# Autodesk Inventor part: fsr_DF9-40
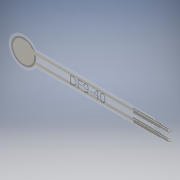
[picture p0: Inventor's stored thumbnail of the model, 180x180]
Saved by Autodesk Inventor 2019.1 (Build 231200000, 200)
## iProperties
Created: 2018-09
Part Number: fsr_DF9-40
Material: Polycarbonate, Clear
Document SubType Name: Modeling
Designer: Ev
Density: 1.2 g/cm^3
Appearance: Polycarbonate - Clear
Author: Ev
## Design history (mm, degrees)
sketch "Sketch1"
  geometry: L1 (-14.266, 18.616)-(39.487, 18.616); L2 (39.487, 18.616)-(39.487, -35.137); L3 (39.487, -35.137)-(-14.266, -35.137); L4 (-14.266, -35.137)-(-14.266, 18.616); L5 (40.115, 2.406)-(3.888, 2.393); L6 (3.922, -2.407)-(40.115, -2.394); L7 (40.115, -2.394)-(40.115, 2.406); L8 (0.115, -0.042)-(46.724, -0.042); L9 (3.503, 1.565)-(40.115, 1.565); L10 (40.115, 1.565)-(40.115, 0.865); L11 (40.115, 0.865)-(3.753, 0.865); L12 (3.503, -1.65)-(40.115, -1.65); L13 (40.115, -0.95)-(3.753, -0.95); L14 (33.615, 1.915)-(39.615, 1.915); L15 (39.615, 1.915)-(39.615, 0.515); L16 (39.615, 0.515)-(33.615, 0.515); L17 (33.615, 0.515)-(33.615, 1.915); L18 (33.615, -2)-(39.615, -2); L19 (33.615, -0.6)-(33.615, -2); L20 (39.615, -0.6)-(33.615, -0.6); L21 (39.615, -2)-(39.615, -0.6); L22 (33.949, 1.71)-(41.92, 1.71); L23 (42.115, 0.865)-(42.115, 0.88); L24 (41.872, 0.71)-(33.949, 0.71); L25 (33.949, 0.71)-(33.949, 1.71); L26 (42.115, 1.574)-(44.387, 1.574); L27 (44.387, 0.88)-(42.115, 0.88); L28 (42.115, 0.88)-(42.115, 0.865); L29 (42.115, 1.574)-(41.92, 1.71); L30 (42.115, 1.574)-(42.352, 1.574); L31 (42.115, 0.88)-(41.872, 0.71); L32 (42.115, 0.88)-(42.411, 0.88); L33 (45.146, 1.322)-(44.387, 1.574); L34 (45.146, 1.133)-(44.387, 0.88); L35 (44.996, 0.865)-(44.996, 0.861); L36 (41.872, -0.795)-(33.949, -0.795); L37 (33.949, -1.795)-(41.92, -1.795); L38 (42.115, -0.965)-(41.872, -0.795); L39 (42.115, -1.659)-(41.92, -1.795); L40 (42.115, -0.95)-(42.115, -0.965); L41 (42.115, -0.965)-(42.115, -0.95); L42 (42.115, -1.659)-(42.352, -1.659); L43 (42.115, -0.965)-(42.411, -0.965); L44 (44.387, -0.965)-(42.115, -0.965); L45 (42.115, -1.659)-(44.387, -1.659); L46 (44.996, -0.95)-(44.996, -0.946); L47 (45.146, -1.218)-(44.387, -0.965); L48 (45.146, -1.407)-(44.387, -1.659); L49 (33.949, -0.795)-(33.949, -1.795); L50 (40.115, -0.95)-(40.115, -1.65); L51 (14.115, 1.165)-(25.348, 1.165); L52 (25.348, 1.165)-(25.348, -1.457); L53 (25.348, -1.457)-(14.115, -1.457); L54 (14.115, -1.457)-(14.115, 1.165); A1 r 4.5 centre (0.115, -0.042) between (3.899, 2.393) and (3.944, -2.407); A2 r 3.75 centre (0.115, -0.042) between (3.503, 1.565) and (3.753, 0.865); A3 r 3.25 centre (0.115, -0.042) between (2.589, 2.065) and (3.339, 0.365); A4 r 1.46 centre (3.701, 3.011) between (2.589, 2.065) and (3.503, 1.565); A5 r 0.445 centre (3.781, 0.42) between (3.753, 0.865) and (3.339, 0.365); A6 r 0.1 centre (45.115, 1.228) between (45.146, 1.133) and (45.146, 1.322); A7 r 0.1 centre (45.115, -1.312) between (45.146, -1.407) and (45.146, -1.218); A8 r 3.75 centre (0.115, -0.042) between (3.503, -1.65) and (3.753, -0.95); 9 further points; 1 other entity
  constraints: 92 end point, 28 symmetric about line, 20 point on circle, 8 centre point, 7 horizontal, 7 parallel, 6 point on line, 5 perpendicular, 4 tangent, 3 coincident, 2 equal length, 2 horizontal alignment, 2 midpoint, 1 concentric, 5 other
  dimensions: "d9" = 9 diameter of A1; "d12" = 7.5 diameter of A2; "d17" = 40 distance from line of L7 A1.centre; "d22" = 4.8 distance between parallel lines of L6 L5; "d26" = 6.5 diameter of A3; "d27" = 0.7 distance of L9.end L10.end; "d30" = 6 distance of L15.end L16.end; "d31" = 1.4 distance of L14.end L15.end; "d32" = 0.5 distance between parallel lines of L7 L15; "d34" = 0.5 distance from line of L9 A3.start; "d35" = 0.5 distance from line of L11 A3.end; "d37" = 1 distance between parallel lines of L24 L22; "d38" = 2 distance between parallel lines of L23 L10; "d40" = 145 deg angle of L30 L29; "d41" = 145 deg angle of L31 L32; "d42" = 0.2 diameter of A6; "d43" = 0.8 distance of L26.end L33.start; "d44" = 0.8 distance of L27.start L34.start; "d46" = 2 distance from line of L7 L26.start (= d38); "d47" = 5 distance from line of L10 A6.centre; "d78" = 2.54 distance of point (45.215, -1.312) point (45.215, 1.228); "d81" = 2.62167 distance between parallel lines of L53 L51; "d85" = 14 distance from line of L54 point (0.115, -0.042)
  node "Image1"
extrude "Extrusion1" new body sketch "Sketch1" stored distance "d56" = 0.12; taper "d57" = 0 deg
extrude "Extrusion2" new body sketch "Sketch1" stored distance "d58" = 0.07; taper "d59" = 0 deg
extrude "Extrusion3" new body sketch "Sketch1" stored distance "d60" = 0.09; taper "d61" = 0 deg
extrude "Extrusion4" new body sketch "Sketch1" stored distance "d62" = 0.07; taper "d63" = 0 deg
extrude "Extrusion5" new body sketch "Sketch1" stored distance "d64" = 0.4; taper "d66" = 0 deg; dims "d65" = 0.25, "d67" = 0
extrude "Extrusion6" new body sketch "Sketch1" stored distance "d68" = 0.4; taper "d70" = 0 deg; dims "d69" = 0.25, "d71" = 0
extrude "Extrusion7" new body sketch "Sketch1" stored distance "d72" = 0.07; taper "d73" = 0 deg
extrude "Extrusion8" new body sketch "Sketch1" stored distance "d75" = 0.09; taper "d76" = 0 deg
fillet "Fillet1" dims "d77" = 0.08
emboss "Emboss1" sketch "Sketch1" dims "d86" = 0.01, "d87" = 0
node "substrate"
node "conductor"
node "electrode1"
node "conducting_pad1"
node "pad1"
node "pad2"
node "conducting_pad2"
node "electrode2"
other parameters: "d39" = 3
